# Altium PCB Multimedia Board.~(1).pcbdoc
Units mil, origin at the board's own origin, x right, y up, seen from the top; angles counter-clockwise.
Board outline 8820.47 x 865.35 mil, 4 copper layers (Top Layer, InternalPlane1, InternalPlane2, Bottom Layer); 37 components, 38 nets, 94 pads, 30 vias.
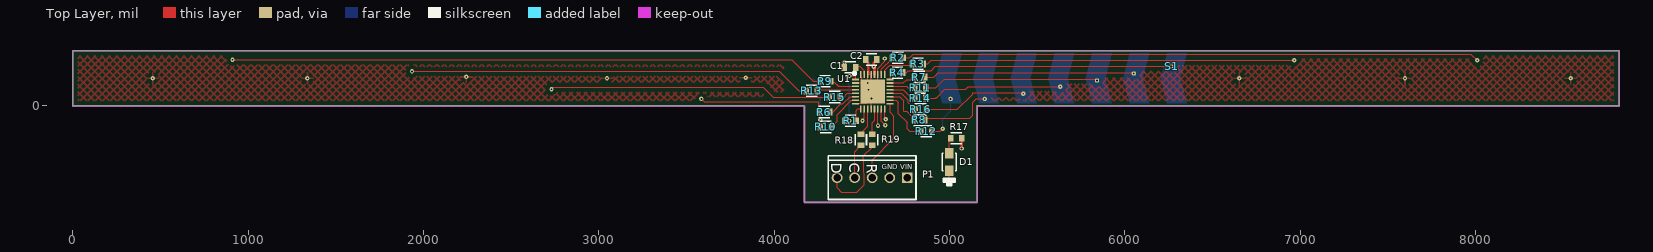
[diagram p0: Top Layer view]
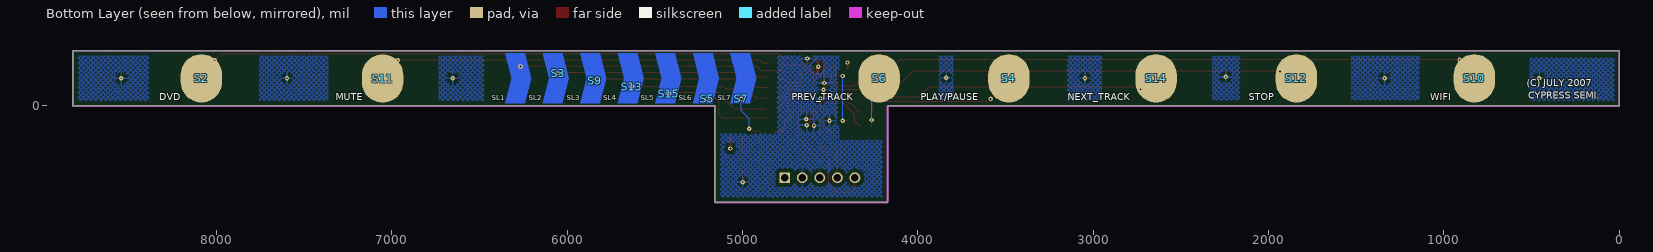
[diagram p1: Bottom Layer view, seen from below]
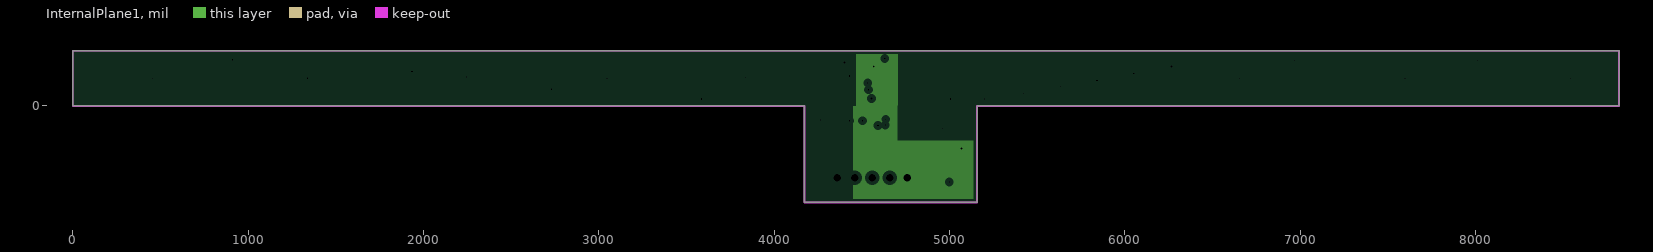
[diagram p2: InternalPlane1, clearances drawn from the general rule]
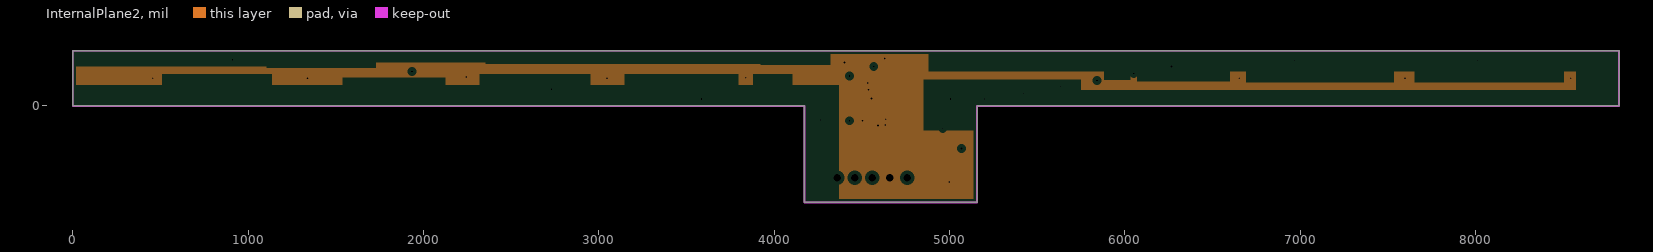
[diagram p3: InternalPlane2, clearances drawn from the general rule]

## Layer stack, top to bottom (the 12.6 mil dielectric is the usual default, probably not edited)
Top Layer: signal copper 1.4
Dielectric: prepreg 12.6, FR-4, Dk 4.8
InternalPlane1: plane copper 1.4, net VCC
Dielectric: prepreg 12.6, FR-4, Dk 4.8
InternalPlane2: plane copper 1.4, net GND
Dielectric: core 12.6, FR-4, Dk 4.8
Bottom Layer: signal copper 1.4

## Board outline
0,0 4172.05,0.39 4172.05,-550.39 5157.87,-550.39 5157.87,0.39 8820.47,0.39 8820.47,314.57 0,314.96

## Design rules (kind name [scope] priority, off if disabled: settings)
Clearance Clearance_1 [All vs InPoly] p1: gap=20
Clearance [All] p2: gap=7
ComponentClearance [All] p1 off: gap=10 collisioncheckmode=3 verticalgap=10
DiffPairsRouting [All] p1 off: maxlimit=10 minlimit=10 mostfreqgap=10 maxuncoupledlength=500
FanoutControl Fanout_BGA [IsBGA] p1 off: bgadir=Out bgaviamode=Centered fanoutstyle=Auto fanoutdirection=Alternating viagrid=1 // Fanout_BGA (Default Rule)
FanoutControl Fanout_LCC [IsLCC] p2 off: bgadir=Out bgaviamode=Centered fanoutstyle=Auto fanoutdirection=Alternating viagrid=1 // Fanout_LCC (Default Rule)
FanoutControl Fanout_SOIC [IsSOIC] p3 off: bgadir=Out bgaviamode=Centered fanoutstyle=Auto fanoutdirection=Alternating viagrid=1 // Fanout_SOIC (Default Rule)
FanoutControl Fanout_Small [(CompPinCount < 5)] p4 off: bgadir=Out bgaviamode=Centered fanoutstyle=Auto fanoutdirection=OutThenIn viagrid=1 // Fanout_Small (Default Rule)
FanoutControl Fanout_Default [All] p5 off: bgadir=Out bgaviamode=Centered fanoutstyle=Auto fanoutdirection=Alternating viagrid=1 // Fanout_Default (Default Rule)
HoleSize [All] p1: absolutevalues=TRUE maxlimit=150 minlimit=10 maxpercent=80.000 minpercent=20.000
MatchedLengths [InNetClass('ITO signals')] p1: tolerance=1000 amplitude=200 gap=20 style=Round
PlaneClearance [All] p1: clearance=20
PlaneConnect [All] p1: planeconnectstyle=Relief reliefexpansion=20 reliefentries=4 reliefconductorwidth=10 reliefairgap=10
PolygonConnect [All] p1: connectstyle=Relief reliefconductorwidth=10 reliefentries=4 polygonreliefangle="90 Angle"
RoutingTopology [All] p1 off: topology=Shortest
RoutingVias [All] p1: holewidth=10 width=25 viastyle="Through Hole" minholewidth=10 minwidth=25 maxholewidth=10 maxwidth=25
SMDNeckDown [All] p1 off: percent=80.000
SMDToPlane SMDToPlane_1 [InNet('VDD')] p1 off: distance=300000
SMDToPlane [InNet('GND')] p2 off: distance=300000
SolderMaskExpansion [All] p1: expansion=3
TestPointUsage [All] p1: valid=0 allowmultiple=FALSE
Testpoint [All] p1: side=15 testpointundercomponent=TRUE minsize=40 maxsize=100 preferedsize=60 minholesize=0 maxholesize=40 preferedholesize=32 testpointgrid=1 style=1023 order=0-112345678
Width [All] p1: maxlimit=100 minlimit=7 preferedwidth=7 minimp=50.000000 maximp=50.000000 favimp=50.000000
8 further rules are at their usual default settings.

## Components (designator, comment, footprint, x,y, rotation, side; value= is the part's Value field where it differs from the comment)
C1 "0.1uF, 0603" 0603 4464.52,220 r180 top
C2 "0.1uF, 0603" 0603 4586.76,264.94 r180 top
D1 "LED" 0805LED 4999.52,-269.29 r270 top
P1 "ISSP_CON" ISPCON 4759.52,-409.29 r180 top
R1 "1K" 0603 4404.52,-84.29 r0 top
R2 "560 OHM" 0603 4736.76,274.94 r180 top
R3 "560 OHM" 0603 4851.76,239.94 r180 top
R4 "560 OHM" 0603 4734.75,189.94 r180 top
R6 "560 OHM" 0603 4316.76,-35.06 r180 top
R7 "560 OHM" 0603 4859.75,164.94 r180 top
R8 "560 OHM" 0603 4797.01,-80 r0 top
R9 "560 OHM" 0603 4259.52,140.71 r0 top
R10 "560 OHM" 0603 4326.76,-120.06 r180 top
R11 "560 OHM" 0603 4864.76,104.02 r180 top
R12 "560 OHM" 0603 4836.76,-145.06 r0 top
R13 "560 OHM" 0603 4184.52,85.71 r0 top
R14 "560 OHM" 0603 4864.75,44.94 r180 top
R15 "560 OHM" 0603 4314.52,50.71 r0 top
R16 "560 OHM" 0603 4866.76,-20.06 r180 top
R17 "330 OHM, 0603" 0603 5069.52,-184.29 r180 top
R18 "300 OHM" 0603 4495,-162.01 r270 top
R19 "300 OHM" 0603 4560,-162.01 r270 top
S1 "SL1" CAPSENSE_PAD 6266.85,225.04 r180 top
S2 "DVD" "BUTTON 9mm no silk"#1 7999.52,112.71 r180 top
S3 "SL2" CAPSENSE_PAD 6051.68,185.02 r0 bottom
S4 "PLAY/PAUSE" "BUTTON 9mm no silk"#2 3902.52,92.71 r180 top
S5 "SL6" CAPSENSE_PAD 5201.61,39.96 r0 bottom
S6 "PREV_TRACK" "BUTTON 9mm no silk"#3 4495.52,147.71 r180 top
S7 "SL7" CAPSENSE_PAD 5006.69,40.04 r0 bottom
S9 "SL3" CAPSENSE_PAD 5841.68,145.02 r0 bottom
S10 "WIFI" "BUTTON 9mm no silk"#4 2070.52,87.71 r180 top
S11 "MUTE" "BUTTON 9mm no silk"#5 7252.27,105.94 r180 top
S12 "STOP" "BUTTON 9mm no silk"#6 2556.52,92.71 r180 top
S13 "SL4" CAPSENSE_PAD 5631.69,110.04 r0 bottom
S14 "NEXT_TRACK" "BUTTON 9mm no silk"#7 3124.51,72.7 r180 top
S15 "SL5" CAPSENSE_PAD 5421.69,70.04 r0 bottom
U1 "CY8C21434-32PIN" 32-MLF 4464.52,150.71 r0 top

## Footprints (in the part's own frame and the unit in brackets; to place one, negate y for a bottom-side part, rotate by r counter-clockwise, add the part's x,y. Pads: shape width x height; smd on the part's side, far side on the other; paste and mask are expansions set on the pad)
32-MLF [mm]
  rect 3.5x3.5 smd: 0(2.5,-1.75)
  rect 1x0.23 smd: 1(0,0) 2(0,-0.5) 3(0,-1) 4(0,-1.5) 5(0,-2) 6(0,-2.5) 7(0,-3) 8(0,-3.5) 17(5,-3.5) 18(5,-3) 19(5,-2.5) 20(5,-2) 21(5,-1.5) 22(5,-1) 23(5,-0.5) 24(5,0)
  rect 0.23x1 smd: 9(0.75,-4.25) 10(1.25,-4.25) 11(1.75,-4.25) 12(2.25,-4.25) 13(2.75,-4.25) 14(3.25,-4.25) 15(3.75,-4.25) 16(4.25,-4.25) 25(4.25,0.75) 26(3.75,0.75) 27(3.25,0.75) 28(2.75,0.75) 29(2.25,0.75) 30(1.75,0.75) 31(1.25,0.75) 32(0.75,0.75)
  silkscreen extent -0.35,0.7 0.05,1.1
0603 [mm]
  rect 0.8x1 smd: 1(0,0) 2(1.6,0)
  silkscreen extent 0,-0.81 1.58,0.81
0805LED [mil]
  rect 60x50 smd: 1(0,0) 2(100,0)
  silkscreen extent 0,-40 187,40
"BUTTON 9mm no silk"#1 [mm]
  oval 6x7 smd far side: 1(-2.216,-1.137)
"BUTTON 9mm no silk"#2 [mm]
  oval 6x7 smd far side: 1(10.687,-1.645)
"BUTTON 9mm no silk"#3 [mm]
  oval 6x7 smd far side: 1(6.953,-0.248)
"BUTTON 9mm no silk"#4 [mm]
  oval 6x7 smd far side: 1(31.591,-1.772)
"BUTTON 9mm no silk"#5 [mm]
  oval 6x7 smd far side: 1(5.074,-1.264)
"BUTTON 9mm no silk"#6 [mm]
  oval 6x7 smd far side: 1(18.155,-1.645)
"BUTTON 9mm no silk"#7 [mm]
  oval 6x7 smd far side: 1(12.263,-2.152)
CAPSENSE_PAD [mil] "CAPSENSE_PAD"
  round 25 hole 10: 1(0.08,0.08)
ISPCON [mil]
  rect 62x62 hole 42: 1(0,0)
  round 62 hole 42: 2(100,0) 3(200,0) 4(300,0) 5(400,0)
  silkscreen extent -50,-125 450,125

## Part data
C1 C2: library part CAP, "Capacitor"
D1: "BLUE"
P1: "PSoC Programming Connector"
R1 R2 R3 R4 R6 R7 R8 R9 R10 R11 R12 R13 R14 R15 R16 R17 R18 R19: library part RES, "RESISTOR"
S1 S2 S3 S4 S5 S6 S7 S9 S10 S11 S12 S13 S14 S15: library part "CAPSENSE BUTTON"
U1: library part CY8C21434-24LFXI, "32  MLF"

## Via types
v1: diameter 25, hole 10, Top Layer to Bottom Layer, tented both sides, 16 vias
v2: diameter 25, hole 10, Top Layer to Bottom Layer, 14 vias

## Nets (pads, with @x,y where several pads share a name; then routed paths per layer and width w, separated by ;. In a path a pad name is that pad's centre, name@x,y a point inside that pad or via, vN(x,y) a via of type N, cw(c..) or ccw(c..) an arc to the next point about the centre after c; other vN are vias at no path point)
GND: C1.2 C2.2 D1.2 P1.2 U1.0 U1.2 U1.8 U1.10 U1.12 U1.14 U1.15 U1.16 U1.27 U1.29 U1.30 U1.32 | length 1127.4
  Top Layer w7: U1.8 4479.02,12.91 4481.82,15.71 4529.52,15.71 v2(4555.52,41.71) U1.12 ; U1.2 4534.21,131.02 v2(4534.52,130.71) ; U1.2@4479.41,131.02 U1.2@4479.72,130.71 ; U1.32 4494.05,165.74 4498.7,161.08 4498.7,131.52 v2(4538.52,91.71) ; v2(4504.52,-84.29) 4513.73,-75.08 U1.10 ; U1.30@4534.52,179.13 v2(4534.52,130.71) ; U1.30@4535.62,180.24 U1.29 4553.1,137.13 4546.68,130.71 v2(4534.52,130.71) ; U1.30@4536.53,191.14 4541.53,186.14 ; U1.0@4590.42,130.71 4592.47,132.76 4592.47,216.25 4594.44,216.25 4631.69,253.5 v2(4631.69,270.83) ; v2(4592.47,-112.24) U1.14 ; U1.15 4612.16,-86.93 v2(4634.52,-109.29) ; U1.16 4631.84,-71.61 v2(4636.52,-76.29) ; v2(4999.52,-434.29) D1.2
  Top Layer w10: C1.2@4401.53,210.71 v2(4401.53,247.72) ; 4541.53,186.14 4547.2,186.14
  Top Layer w15: U1.30@4536.53,191.14 C2.2@4536.53,245.71
  other v1: 456.69,157.48 1338.58,157.48 3047.24,157.48 6653.54,157.48 7598.43,157.48 8543.31,157.48 3838.58,161.42 2244.09,165.35
NetC1_1: C1.1 R1.1 U1.1 U1.31 | length 461.7
  Top Layer w7: R1.1 v2(4429.52,-84.29) ; v2(4429.52,170.71) 4464.52,170.71 ; U1.1 4464.52,210.71 4479.52,225.71 4489.52,225.71 4513.73,201.5 U1.31
  Bottom Layer w7: v2(4429.52,-84.29) v2(4429.52,170.71)
NetD1_1: D1.1 R17.2 | length 87.9
  Top Layer w7: D1.1 4999.52,-191.3 R17.2
NetR1_2: R1.2 U1.9 | length 88
  Top Layer w7: R1.2 4467.52,-27.29 4478.2,-16.61 U1.9
NetR2_1: R2.1 S2.1 | length 3296.4
  Top Layer w7: R2.1 4773.21,274.94 4793.48,295.21 7974.68,295.21 v1(8010.08,259.84)
NetR2_2: R2.2 U1.26 | length 120.2
  Top Layer w7: U1.26 4612.16,208.38 4673.76,269.98 R2.2
NetR3_1: R3.1 S11.1 | length 2134.4
  Top Layer w7: R3.1 4876.01,239.94 4895.89,259.83 v1(6966.77,259.84)
  Bottom Layer w7: v1(6966.77,259.84) S11.1@6974.63,251.95
NetR3_2: R3.2 U1.25 | length 190.8
  Top Layer w7: U1.25 4631.84,204.44 4659.67,232.27 4776.09,232.27 R3.2@4783.76,239.94
NetR4_1: R4.1 S1.1 | length 1546.5
  Top Layer w7: R4.1 4755.14,189.94 4765.97,200.77 4895.89,200.77 4920.06,224.94 S1.1@6266.76,224.94
NetR4_2: R4.2 U1.24 | length 50.6
  Top Layer w7: U1.24 4661.37,179.56 R4.2@4676.76,194.94
NetR6_1: R6.1 U1.6 | length 183.9
  Top Layer w7: R6.1 4333.29,-35.06 4380.06,11.71 4392.52,11.71 4433.09,52.28 U1.6
NetR6_2: R6.2 S4.1 | length 733.4
  Top Layer w7: v1(3585.63,40.12) 3602.14,23.61 4253.37,23.61 4253.76,23.21 R6.2
NetR7_1: R7.1 S3.1 | length 1203.6
  Top Layer w7: R7.1 4911.24,164.94 4935.26,188.96 6047.74,188.96 S3.1@6051.76,184.94
NetR7_2: R7.2 U1.23 | length 149.4
  Top Layer w7: U1.23 4737.29,131.02 4755.86,149.59 4781.4,149.59 R7.2
NetR8_1: R8.1 U1.19 | length 221.2
  Top Layer w7: U1.19 4717.95,52.28 4739.52,30.71 4739.52,-29.29 4755.99,-29.29 R8.1@4796.76,-70.06
NetR8_2: R8.2 S5.1 | length 430.3
  Top Layer w7: R8.2@4859.75,-70.06 5115.54,-70.06 5132.11,-53.48 5132.11,19.67 5152.31,39.87 S5.1
NetR9_1: R9.1 S10.1 | length 3398.9
  Top Layer w7: v1@911.64,263.76 4100.61,263.76 4223.67,140.71 R9.1
  other v1: 911.65,263.78
NetR9_2: R9.2 U1.3 | length 147.1
  Top Layer w7: R9.2@4327.51,135.71 4342.51,135.71 4366.88,111.34 U1.3
NetR10_1: R10.1 U1.7 | length 223.3
  Top Layer w7: R10.1 4359.52,-87.29 4359.52,-49.29 4441.41,32.6 U1.7
NetR10_2: R10.2 S6.1 | length 294.9
  Top Layer w7: R10.2 v1(4263.78,-80.47)
  Bottom Layer w7: S6.1 4262.03,117.19 4262.03,-78.76 v1(4263.78,-80.47)
NetR11_1: R11.1 S9.1 | length 1005.7
  Top Layer w7: R11.1@4859.75,104.94 4922.11,104.94 4970.69,153.53 5833.17,153.53 S9.1@5841.76,144.94
NetR11_2: R11.2 U1.22 | length 138
  Top Layer w7: U1.22 4756.98,111.34 4763.37,104.94 R11.2@4796.76,104.94
NetR12_1: R12.1 U1.18 | length 308.8
  Top Layer w7: U1.18 4697.63,32.6 4709.52,20.71 4709.52,-44.29 4759.52,-94.29 4759.52,-131.36 4773.21,-145.06 R12.1
NetR12_2: R12.2 S7.1 | length 256.7
  Top Layer w7: R12.2 4946.44,-145.06 v1(4961.57,-129.92)
  Bottom Layer w7: v1(4961.57,-129.92) 4961.56,-72.14 5006.76,-26.95 S7.1@5006.76,39.94
NetR13_1: R13.1 S12.1 | length 2295.3
  Top Layer w7: v1@1935.26,196.83 4029.75,196.83 4140.87,85.71 R13.1
  other v1: 1935.28,196.85
NetR13_2: R13.2 U1.4 | length 212.4
  Top Layer w7: R13.2@4252.51,90.71 4253.46,91.65 U1.4
NetR14_1: R14.1 S13.1 | length 796.6
  Top Layer w7: R14.1 4925.73,44.94 4925.73,49.51 4929.67,49.51 4974.63,94.47 5092.74,94.47 5108.21,109.94 S13.1@5631.76,109.94
NetR14_2: R14.2 U1.21 | length 160.5
  Top Layer w7: U1.21 4738.58,91.65 4738.58,90.37 4784,44.94 R14.2
NetR15_1: R15.1 S14.1 | length 1607
  Top Layer w7: v1@2730.54,106.28 3939.2,106.28 3994.77,50.71 R15.1
  other v1: 2730.55,94.49
NetR15_2: R15.2 U1.5 | length 95.8
  Top Layer w7: R15.2 4397.52,50.71 4418.78,71.97 U1.5
NetR16_1: R16.1 S15.1 | length 603.3
  Top Layer w7: R16.1 5045.14,-20.06 5132.11,66.91 5132.11,74.79 5416.91,74.79 S15.1@5423.45,68.25
NetR16_2: R16.2 U1.20 | length 190.2
  Top Layer w7: U1.20 4728.26,71.97 4728.26,69.19 4765.97,31.48 4765.97,17.74 R16.2
NetR18_1: R18.1 U1.11 | length 161.3
  Top Layer w7: R18.1 4495,-155 4533.42,-116.58 U1.11
NetR19_1: R19.1 U1.13 | length 150.7
  Top Layer w7: R19.1 4560,-95 4572.79,-82.21 U1.13
SCL: P1.4 R18.2 | length 198.8
  Top Layer w7: P1.4 4460,-280 4460,-260 R18.2
SDA: P1.5 R19.2 | length 483.8
  Top Layer w7: P1.5 4359.52,-467.58 4384.08,-492.14 4470.69,-492.14 4510.06,-452.77 4510,-310 4510,-285 4560,-235 R19.2
VCC: C2.1 P1.1 R17.1 U1.28 | length 144.9
  Top Layer w10: C2.1 C2.1@4586.76,269.94
  Top Layer w15: v2(4569.12,224.39) 4569.12,247.31 C2.1 ; U1.28 v2@4572.79,213.98 ; v2(5069.49,-242.56) R17.1
XRES: P1.3 U1.17 | length 482.6
  Top Layer w7: P1.3 4559.52,-308.83 4683.29,-185.06 4683.29,-59.07 4661.37,-37.15 U1.17

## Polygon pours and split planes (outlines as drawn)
GND on Top Layer "Top Layer-GND" (hatched 45Degree grid 30 track 8, remove dead copper, pour order 1000): 6480,-185 5235,-185 5185,-135 5155,-105 5155,410 9260,410 9285,385 9315,355 9315,-185
GND on Top Layer "Top Layer-GND 1" (hatched 45Degree grid 30 track 8, remove dead copper, pour order 1001): -85,380 -95,370 -95,-110 4150,-110 4155,-105 4055,-5 4055,470 0,470 -95,375 -95,370
GND on Bottom Layer "Bottom Layer-GND" (hatched 45Degree grid 20 track 8, remove dead copper, pour order 1002): 4803.15,314.96 4803.15,-157.48 5275.59,-157.48 5275.59,-629.92 4015.75,-629.92 4015.75,-196.85 4448.82,-196.85 4448.82,314.96
GND on Bottom Layer "Bottom Layer-GND 1" (hatched 45Degree grid 20 track 7.99, remove dead copper, pour order 1003): 3799.21,428.41 3799.21,-99.15 3877.95,-99.15 3877.95,428.41
GND on Bottom Layer "Bottom Layer-GND 2" (hatched 45Degree grid 20 track 7.99, pour order 1004): 2952.76,291.34 3149.61,291.34 3149.61,23.62 2952.76,23.62
GND on Bottom Layer "Bottom Layer-GND 3" (hatched 45Degree grid 20 track 7.99, remove dead copper, pour order 1005): 2165.35,283.46 2322.83,283.46 2322.83,31.5 2165.35,31.5
GND on Bottom Layer "Bottom Layer-GND 4" (hatched 45Degree grid 20 track 7.99, remove dead copper, pour order 1006): 1141.73,283.46 1527.56,283.46 1527.56,31.5 1141.73,31.5
GND on Bottom Layer "Bottom Layer-GND 5" (hatched 45Degree grid 20 track 7.99, remove dead copper, pour order 1007): 511.81,275.59 511.81,23.62 15.75,23.62 15.75,275.59
GND on Bottom Layer "Bottom Layer-GND 6" (hatched 45Degree grid 20 track 7.99, pour order 1008): 6476.38,295.28 6476.38,19.68 6732.28,19.68 6732.28,295.28 6476.38,295.28
GND on Bottom Layer "Bottom Layer-GND 7" (hatched 45Degree grid 20 track 7.99, remove dead copper, pour order 1009): 7362.2,295.28 7362.2,19.68 7755.91,19.68 7755.91,295.28 7362.2,295.28
GND on Bottom Layer "Bottom Layer-GND 8" (hatched 45Degree grid 20 track 7.99, remove dead copper, pour order 1010): 8385.83,295.28 8385.83,19.68 8799.21,19.68 8799.21,295.28
VCC on InternalPlane1 (split plane): 4709.53,294.36 4709.53,0 4704.72,0 4704.72,-196.85 5137.48,-196.85 5137.48,-530 4448.82,-530 4448.82,0 4464.53,0 4464.53,294.37
GND on InternalPlane2 (split plane): 8800.08,294.18 8800.08,196.85 8574.8,196.85 8574.8,90 5750,90 5750,150 4854.72,150 4854.72,67.01 4855,67.01 4855,-140 5137.48,-140 5137.48,-530 4192.44,-530 4192.44,0.39 4192.44,0.4 4191.72,3.99 4190.89,8.2 4188.83,11.27 4186.47,14.81 4183.29,16.94 4179.85,19.23 4176.14,19.97 4172.05,20.79 20.39,20.39 20.39,225 1130,225 1130,250 2355,250 2355,240 3163.61,240 3163.61,239.79 3925,239.79 3925,235 4320,235 4320,294.38

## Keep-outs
Keep-Out Layer:
  lines w10: 0,0 4173.23,0 4173.23,-551.18 5157.48,-551.18 5157.48,0 8818.9,0 8818.9,314.96 0,314.96 0,0

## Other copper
Top Layer:
  region: 4553.1,-16.61 4555.52,41.71
  region: 4374.52,111.34 4342.51,135.71
  text "TOP COPPER (.GTL)" at 925,3650 h40
Bottom Layer:
  region net NetR12_2: 4958.42,300.94 4921.88,158.82 4958.42,15.94 5069.52,15.94 5032.98,158.82 5069.76,300.94
  region net NetR8_2: 5171.42,300.94 5134.88,158.82 5171.42,15.94 5282.52,15.94 5245.98,158.82 5282.76,300.94
  region net NetR16_1: 5386.42,300.94 5349.88,158.82 5386.42,15.94 5497.52,15.94 5460.98,158.82 5497.76,300.94
  region net NetR14_1: 5600.42,300.94 5563.88,158.82 5600.42,15.94 5711.52,15.94 5674.98,158.82 5711.76,300.94
  region net NetR11_1: 5814.42,300.94 5777.88,158.82 5814.42,15.94 5925.52,15.94 5888.98,158.82 5925.76,300.94
  region net NetR7_1: 6028.42,300.94 5991.88,158.82 6028.42,15.94 6139.52,15.94 6102.98,158.82 6139.76,300.94
  region net NetR4_1: 6242.42,299.94 6205.88,157.82 6242.42,14.94 6353.52,14.94 6316.98,157.82 6353.76,299.94
  region: 4414.52,155.71 4374.52,155.71 4414.52,155.71
  text "BOTTOM COPPER (.GBL)" at 925,3200 h40
InternalPlane1 (plane layer: these items are gaps in the copper):
  rectangle: 4704.72,-196.85 5157.48,0
  rectangle: 0,0 4464.53,314.96
  rectangle: 4709.53,0 8818.9,314.96
  rectangle: 4173.23,-551.18 4448.82,0
  text "INTERNAL PLANE 1 (.GP1)" at 925,3500 h40
InternalPlane2 (plane layer: these items are gaps in the copper):
  rectangle: 3935,240 3945,255
  rectangle: 1110,250 2380,305
  rectangle: 5140,10 6435,90
  rectangle: 4855,-140 5157.87,80
  rectangle: 6410,10 8805,90
  rectangle: 3925,235 4320,310
  rectangle: 3163.61,239.79 3945,314.79
  rectangle: 2355,240 3230,315
  rectangle: 0,225 1130,300
  rectangle: 1540,85 2125,160
  rectangle: 3149.61,118.11 3795.28,181.1
  rectangle: 3881.89,118.11 4102.36,181.1
  rectangle: 4854.72,67.01 5750,150
  rectangle: 5881.89,149.61 6031.5,196.85
  rectangle: 6070.87,141.73 6598.43,196.85
  rectangle: 6692.91,133.86 7535.43,196.85
  rectangle: 7653.54,133.86 8503.94,196.85
  rectangle: 8574.8,90 8803.15,196.85
  region: 1106.81,218.11 1728.86,218.11 1728.86,281.1 1106.81,281.1
  region: 0,118.11 0,0 4173.23,0 4173.23,-551.18 4370.08,-551.18 4370.08,118.11
  region: 4881.89,314.96 4881.89,196.85 8818.9,196.85 8818.9,314.96
  region: 511.81,118.11 1133.86,118.11 1133.86,181.1 511.81,181.1
  region: 2322.83,125.98 2322.83,181.1 2952.76,181.1 2952.76,118.11 2322.83,118.11
  text "INTERNAL PLANE 2 (.GP2)" at 925,3350 h40

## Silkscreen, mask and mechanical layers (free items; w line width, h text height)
Top Overlay:
  text "TOP OVERLAY (.GTO)" at 925,3900 h40
Bottom Overlay:
  text "BOTTOM SILKSCREEN (.GBO)" at 925,3050 h40
  text "(C) JULY 2007" at 526.77,111.02 h40
  text "CYPRESS SEMI." at 518.11,42.13 h40
Top Paste:
  text "TOP PASTE (.GTP)" at 2775,3250 h40
Bottom Paste:
  lines w10: 0,0 0,314.96 8818.9,314.96 8818.9,0 5157.48,0 5157.48,-551.18 4173.23,-551.18 4173.23,0 0,0
  text "BOTTOM PASTE (.GBP)" at 2775,3100 h40
Top Solder:
  text "TOP SOLDERMASK (.GTS)" at 925,3775 h40
Bottom Solder:
  text "BOTTOM SOLDERMASK (.GBS)" at 925,2900 h40
Mechanical 1:
  lines w10: 0,0 4173.23,0 4173.23,-551.18 5157.48,-551.18 5157.48,0 8818.9,0 8818.9,314.96 0,314.96 0,0
Drill Drawing:
  lines w10: 4225.29,4073.51 4225.29,5173.51 cw(c4325.29,5173.51) 4325.29,5273.51 9875.29,5273.51 cw(c9875.29,5173.51) 9975.29,5173.51 9975.29,4073.51 cw(c9875.29,4073.51) 9875.29,3973.51 4324.53,3973.53 cw(c4326.29,4074.51) 4225.29,4074.51 ; 4700.29,4123.51 4800.29,4123.51 ; 5300.29,4123.51 5400.29,4123.51 ; 5525.29,4223.51 4325.29,4223.51 ccw(c4325.29,4173.51) 4275.29,4173.51 4275.29,4073.51 ccw(c4325.29,4073.51) 4325.29,4023.51 5525.29,4025.51 ccw(c5525.29,4073.51) 5573.29,4073.51 ; 5525.29,4273.51 4325.29,4273.51 cw(c4325.29,4323.51) 4275.29,4323.51 4275.29,5173.51 cw(c4325.29,5173.51) 4325.29,5223.51 5525.29,5223.51 ; 5525.29,4275.51 ccw(c5525.29,4323.51) 5573.29,4323.51 ; 5526.29,4223.51 cw(c5526.29,4174.51) 5575.29,4174.51 ; 5526.29,5223.51 cw(c5526.29,5174.51) 5575.29,5174.51 ; 5575.29,4073.51 5575.29,4173.51 ; 5575.29,4323.51 5575.29,5173.51 ; 5674.42,4023.52 cw(c5675.29,4073.51) 5625.29,4073.51 5625.29,4173.51 cw(c5675.29,4173.51) 5675.29,4223.51 7350.29,4223.51 cw(c7350.29,4173.51) 7400.29,4173.51 7400.29,4073.51 ; 5674.42,4273.52 cw(c5675.29,4323.51) 5625.29,4323.51 5625.29,4548.51 cw(c5675.29,4548.51) 5675.29,4598.51 6425.29,4598.51 ; 5675.29,4023.51 7350.29,4023.51 ; 5675.29,4273.51 6425.29,4273.51 ; 6424.58,4598.48 cw(c6426.29,4549.51) 6475.29,4549.51 ; 6425.29,4648.51 5675.29,4648.51 cw(c5675.29,4698.51) 5625.29,4698.51 5625.29,4923.51 cw(c5675.29,4923.51) 5675.29,4973.51 6425.29,4973.51 ; 6426.29,4273.51 ccw(c6426.29,4322.51) 6475.29,4322.51 ; 6426.29,4973.51 cw(c6426.29,4924.51) 6475.29,4924.51 ; 6427.29,4648.51 ccw(c6427.29,4696.51) 6475.29,4696.51 ; 6475.29,4323.51 6475.29,4548.51 ; 6475.29,4698.51 6475.29,4923.51 ; 6525.29,4322.51 ccw(c6574.29,4322.51) 6574.29,4273.51 8176.29,4273.51 ccw(c8176.29,4322.51) 8225.28,4323.37 ; 6525.29,4323.51 6525.29,4448.51 cw(c6575.29,4448.51) 6575.29,4498.51 8175.29,4498.51 ; 6525.29,4597.51 ccw(c6574.29,4597.51) 6574.29,4548.51 ; 6525.29,4598.51 6525.29,4923.51 cw(c6575.29,4923.51) 6575.29,4973.51 8625.29,4973.51 cw(c8625.29,4923.51) 8675.29,4923.51 8675.29,4598.51 cw(c8625.29,4598.51) 8626.16,4548.51 ; 6575.29,4548.51 8625.29,4548.51 ; 7351.45,4023.51 ccw(c7352.29,4071.51) 7400.27,4073.19 ; 7499.42,4023.52 cw(c7500.29,4073.51) 7450.29,4073.51 7450.29,4173.51 cw(c7500.29,4173.51) 7500.29,4223.51 9175.29,4223.51 cw(c9175.29,4173.51) 9225.29,4173.51 9225.29,4073.51 ; 7500.29,4023.51 9175.29,4023.51 ; 8176.29,4498.51 cw(c8176.29,4449.51) 8225.29,4449.51 ; 8225.29,4323.51 8225.29,4448.51 ; 8275.29,4323.51 8275.29,4448.51 ; 8275.29,4324.51 ccw(c8326.29,4324.51) 8325.4,4273.52 ; 8275.36,4448 cw(c8323.29,4450.51) 8323.29,4498.51 ; 8325.29,4273.51 8625.29,4273.51 ccw(c8625.29,4323.51) 8675.29,4323.51 8675.29,4448.51 ; 8325.29,4498.51 8625.29,4498.51 ; 8626.29,4498.51 cw(c8626.29,4449.51) 8675.29,4449.51 ; 8725.29,4322.51 ccw(c8774.29,4322.51) 8775.15,4273.52 ; 8725.29,4323.51 8725.29,4448.51 cw(c8775.29,4448.51) 8775.29,4498.51 9875.29,4498.51 ; 8775.29,4273.51 9875.29,4273.51 ccw(c9875.29,4323.51) 9925.29,4323.51 9925.29,4449.51 ccw(c9876.29,4449.51) 9876.29,4498.51 ; 9176.45,4023.51 ccw(c9177.29,4071.51) 9225.27,4073.19 ; 9275.29,4072.51 ccw(c9324.29,4072.51) 9325.15,4023.52 ; 9275.29,4073.51 9275.29,4173.51 cw(c9325.29,4173.51) 9325.29,4223.51 9875.29,4223.51 cw(c9875.29,4173.51) 9925.29,4174.38 ; 9325.29,4023.51 9875.29,4023.51 ccw(c9875.29,4073.51) 9925.29,4073.51 9925.29,4173.51 ; 9874.58,5223.48 cw(c9876.29,5174.51) 9925.29,5174.51 ; 9875.29,5223.51 8775.29,5223.51 ccw(c8775.29,5173.51) 8725.29,5173.51 8725.29,4598.51 ccw(c8775.29,4598.51) 8775.29,4548.51 9875.29,4548.51 ccw(c9875.29,4598.51) 9925.29,4598.51 9925.29,5173.51 ; 0,0 4173.23,0 4173.23,-551.18 5157.48,-551.18 5157.48,0 8818.9,0 8818.9,314.96 0,314.96 0,0 ; 5625.29,5073.51 ccw(c5675.29,5073.51) 5675.29,5023.51 8625.29,5023.51 ccw(c8625.29,5073.51) 8675.29,5073.51 8675.29,5173.51 ccw(c8625.29,5173.51) 8625.29,5223.51 5675.29,5223.51 ccw(c5675.29,5173.51) 5625.29,5173.51 5625.29,5073.51
  text "NOTES:" at 4780.71,6205.51 h40
  text "LAYER STACK:" at 7190.71,6195.51 h40
  text "1. MATERIAL: 4 LAYERS, FR4,  0.062\" +/-10% IN. THK." at 4780.71,6087.4 h40
  text "LAYER 1  .GTL" at 7190.71,6077.4 h40
  text ".LEGEND" at 10127.17,6071.65 h40
  text "2. 1 OZ. COPPER THICKNESS." at 4780.71,5969.29 h40
  text "LAYER2   .GP1" at 7190.71,5959.29 h40
  text "3. SOLDERMASK: TWO SIDES, LPI." at 4780.71,5851.18 h40
  text "LAYER3   .GP2" at 7190.71,5841.18 h40
  text "4. HOLE SIZES: FINISHED SIZES LISTED." at 4780.71,5733.07 h40
  text "LAYER4   .GBL" at 7190.71,5723.07 h40
  text "5. MINIMUM SPACE .007'', MINIMUM TRACE .007''." at 4780.71,5614.96 h40
  text "6. SILKSCREEN: 2 SIDES,  WHITE EPOXY INK." at 4780.71,5496.85 h40
  text "Cypress Semiconductor" at 6334.29,5095.51 h40
  text "CYPRESS SEMICONDUCTOR" at 8764.29,5079.84 h40
  text "DIMs AS NOTED" at 4425.91,5018.07 h40
  text "2700-162ND ST SW" at 8890.29,4943.51 h40
  text "TITLE:" at 6562.79,4886.01 h40
  text "ENGR:" at 5675.29,4873.51 h40
  text "LYNNWOOD, WA 98087" at 8820.29,4833.51 h40
  text "GABRIEL ROWE" at 5769.29,4780.51 h40
  text "USA" at 9210.29,4733.51 h40
  text "CAPSENSE IHR" at 6864.29,4729.84 h40
  text "(425) 787-4896" at 5714.29,4679.84 h40
  text "CAD:" at 5650.29,4493.51 h40
  text "GABRIEL ROWE" at 5840.28,4493.5 h40
  text "PART NO.:" at 6575.29,4411.01 h40
  text "REV:" at 8312.79,4411.01 h40
  text "DATE:" at 8775.29,4411.01 h40
  text "(425) 787-4896" at 5725.28,4343.5 h40
  text "24 JULY 2007" at 8955.28,4328.5 h40
  text "A" at 8489.29,4304.84 h40
  text "MATERIAL" at 4325.29,4148.51 h40
  text "FILE NAME:" at 5675.29,4133.51 h40
  text "LAYER:" at 7515.29,4133.51 h40
  text "GERBER:" at 9335.29,4133.51 h40
  text "SEE NOTES" at 4850.29,4098.51 h40
  text "CAPSENSE_IHR" at 6064.29,4079.84 h40
  text "DRILL AND TRIM(.GD1)" at 925,4075 h40
  text "Copyright 2008 Cypress Semiconductor Corporation." at 4250,3675 h60
  text "This software is owned by Cypress Semiconductor Corporation (Cypress)" at 4225,3450 h60
  text "and is protected by and subject to worldwide patent protection (United" at 4225,3300 h60
  text "String" at 4225,3150 h60
  text "String" at 4225,3000 h60
  text "String" at 4225,2825 h60
  text "String" at 4225,2675 h60
  text "String" at 4225,2525 h60
  text "String" at 4225,2375 h60
  text "String" at 4225,2225 h60
  text "String" at 4225,2075 h60
  text "String" at 4225,1950 h60
  text "String" at 4225,1825 h60
  text "String" at 4225,1700 h60
  text "String" at 4225,1575 h60
  text "String" at 4225,1450 h60
  text "String" at 4225,1325 h60
  text "String" at 4225,1175 h60

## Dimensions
0,0 to 4172.05,-550.39 on Drill Drawing
4173.23,0 to 5157.48,-551.18 on Drill Drawing
0,314.96 to 8818.9,314.96 on Drill Drawing
0,314.96 to 0,0 on Drill Drawing
5157.48,0 to 5157.48,-551.18 on Drill Drawing
4359.52,-409.29 to 4173.23,-551.18 on Drill Drawing
4359.52,-409.29 to 4173.23,-551.18 on Drill Drawing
